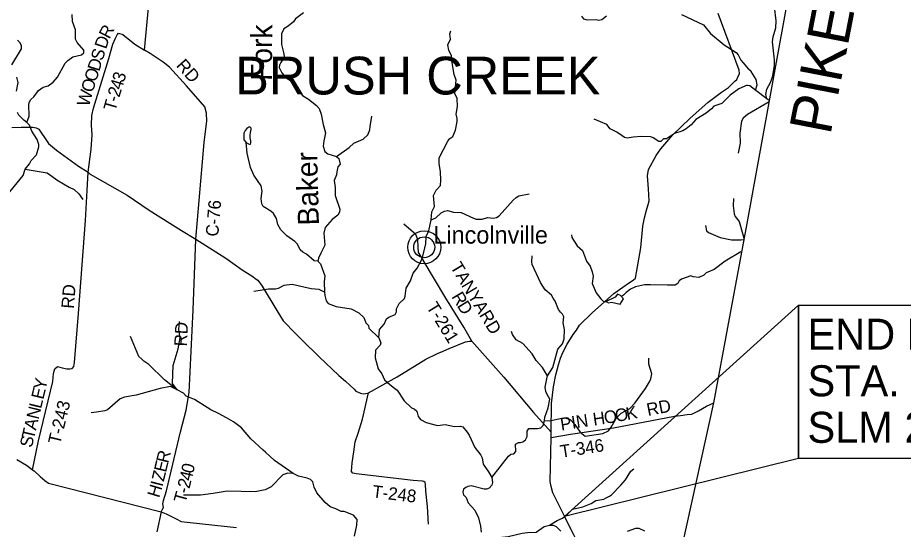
# Model space of a CAD drawing. Extents: x 0 to 34, y 0 to 22.
# Drawn here: x 3.854 to 7.846, y 16.923 to 19.231 of the extents above; entities that cross this region are included whole.
import ezdxf

# ---------------------------------------------------------------- set-up
doc = ezdxf.new("R2010")
doc.units = 0
for name, color, linetype in [('GM_X_Adjacent_County_Text', 7, 'Continuous'), ('GM_X_County', 7, 'Continuous'), ('GM_X_County_Road', 7, 'Continuous'), ('GM_X_County_Road_Text', 7, 'Continuous'), ('GM_X_Major_River', 7, 'Continuous'), ('GM_X_Major_River_Text', 7, 'Continuous'), ('GM_X_Minor_Lake', 7, 'Continuous'), ('GM_X_Minor_River', 7, 'Continuous'), ('GM_X_State_Route', 7, 'Continuous'), ('GM_X_Township_Road', 7, 'Continuous'), ('GM_X_Township_Road_Text', 7, 'Continuous'), ('GM_X_Township_ROW', 7, 'Continuous'), ('GM_X_Township_Text', 7, 'Continuous'), ('GM_X_Unincorporated', 7, 'Continuous'), ('GM_X_Unincorporated_Location', 7, 'Continuous'), ('GM_X_Unincorporated_Text', 7, 'Continuous'), ('SH_Data', 7, 'Continuous')]:
    doc.layers.add(name, color=color, linetype=linetype)

msp = doc.modelspace()

# ---------------------------------------------------------------- linework, layer by layer
at = {"layer": 'GM_X_County'}
msp.add_lwpolyline([(6.5214, 15.204), (6.5756, 15.5109), (6.5797, 15.5314), (6.7601, 16.3985), (6.794, 16.5922), (6.9912, 17.4939), (7.1423, 18.303), (7.4503, 19.9984), (7.5281, 20.392), (7.6111, 20.9006)], dxfattribs=at)
at = {"layer": 'GM_X_County_Road'}
for points in [[(4.6572, 18.2312), (4.6936, 18.6683), (4.7005, 18.7177), (4.7063, 18.7644), (4.7042, 18.8005), (4.6975, 18.8293), (4.6139, 18.9237), (4.5386, 19.0075), (4.5093, 19.0309), (4.4503, 19.0688), (4.4248, 19.0839), (4.4636, 19.5004)], [(3.8496, 17.2378), (3.8934, 17.2122), (3.9205, 17.1914), (3.9273, 17.1862), (3.9544, 17.161), (3.9761, 17.1429), (3.9918, 17.1304), (4.5003, 17.0015), (4.4801, 16.9118)]]:
    msp.add_lwpolyline(points, dxfattribs=at)
at = {"layer": 'GM_X_Major_River'}
for points in [[(5.1417, 19.2532), (5.1063, 19.2259), (5.0967, 19.2127), (5.073, 19.1928), (5.0532, 19.1805), (5.0432, 19.1579), (5.0427, 19.1098), (5.0536, 19.0672), (5.0542, 19.0547), (5.0396, 19.0287), (5.0342, 19.0162), (5.0326, 19.0064), (5.0444, 18.9824), (5.0631, 18.9594), (5.0879, 18.944), (5.1376, 18.8806), (5.1647, 18.864), (5.2004, 18.8345), (5.212, 18.8215), (5.2223, 18.796), (5.2305, 18.7493), (5.2419, 18.7109), (5.2367, 18.6882), (5.2344, 18.6757), (5.2307, 18.6515), (5.2388, 18.6268), (5.2519, 18.6164), (5.2915, 18.6043), (5.3017, 18.5954), (5.3071, 18.57), (5.2967, 18.558), (5.292, 18.5356), (5.2915, 18.5224), (5.2803, 18.4971), (5.2852, 18.4652), (5.2845, 18.4288), (5.3051, 18.3676), (5.3049, 18.3539), (5.2961, 18.34), (5.2713, 18.3205), (5.2399, 18.2841), (5.2336, 18.2587), (5.238, 18.2041), (5.2202, 18.1679), (5.209, 18.1453), (5.207, 18.1324), (5.2186, 18.1201), (5.2385, 18.0661), (5.2356, 18.0388), (5.2363, 17.993), (5.238, 17.9778), (5.2435, 17.9527), (5.2532, 17.9413), (5.2894, 17.9276), (5.3562, 17.9167), (5.3916, 17.8997), (5.4141, 17.8782), (5.4237, 17.8535), (5.4357, 17.8428), (5.4371, 17.8303), (5.4813, 17.7862)], [(5.4813, 17.7862), (5.4913, 17.7638), (5.4882, 17.7539), (5.466, 17.7314), (5.4649, 17.6958), (5.4788, 17.6471), (5.4948, 17.6246), (5.5074, 17.5976), (5.5307, 17.5754), (5.5524, 17.56), (5.5637, 17.5508), (5.5958, 17.5019), (5.6287, 17.4709), (5.6412, 17.4662), (5.6524, 17.4551), (5.6594, 17.4312), (5.6695, 17.4186), (5.6954, 17.405), (5.7456, 17.3905), (5.7801, 17.3951), (5.822, 17.386), (5.85, 17.3883), (5.8602, 17.3845), (5.88, 17.3608), (5.8893, 17.347), (5.9138, 17.2918), (5.941, 17.2567), (5.947, 17.2449), (5.9516, 17.2164), (5.9762, 17.1816), (5.9907, 17.1561), (5.9947, 17.1333), (5.9911, 17.1216), (5.9797, 17.1088), (5.9671, 17.1037), (5.9565, 17.103), (5.8984, 17.1187), (5.8833, 17.1159), (5.8738, 17.1106), (5.8638, 17.1032), (5.8596, 17.0903), (5.8636, 17.0785), (5.876, 17.0667), (5.8844, 17.0427), (5.9147, 17.0083), (5.931, 16.9736), (5.9401, 16.936), (5.9429, 16.9098)]]:
    msp.add_lwpolyline(points, dxfattribs=at)
at = {"layer": 'GM_X_Minor_Lake'}
for points in [[(4.8836, 18.6686), (4.8945, 18.6613), (4.8986, 18.6597), (4.9028, 18.6608), (4.9047, 18.6665), (4.9048, 18.6756), (4.9023, 18.6885), (4.902, 18.7006), (4.9029, 18.7123), (4.9061, 18.7263), (4.9054, 18.7332), (4.9005, 18.7381), (4.8952, 18.7371), (4.8865, 18.7315), (4.8792, 18.7221), (4.873, 18.71), (4.8725, 18.6971), (4.8735, 18.6888), (4.8723, 18.6797)], [(4.8723, 18.6797), (4.8836, 18.6686)], [(6.5706, 17.9775), (6.5581, 17.9833), (6.5463, 17.9705), (6.5071, 17.9497), (6.5173, 17.9439), (6.5305, 17.9468), (6.5694, 17.9388), (6.5844, 17.9629)], [(6.5844, 17.9629), (6.5706, 17.9775)]]:
    msp.add_lwpolyline(points, dxfattribs=at)
at = {"layer": 'GM_X_Minor_River'}
for points in [[(7.2301, 18.867), (7.2266, 18.8843), (7.2308, 18.9082), (7.248, 18.9409), (7.2583, 18.9689), (7.2651, 19.0158), (7.2647, 19.0409), (7.2561, 19.1226), (7.2591, 19.1446), (7.2707, 19.1846), (7.2731, 19.2172), (7.2654, 19.2807), (7.2735, 19.3656), (7.2935, 19.4041), (7.3308, 19.4654)], [(3.8944, 18.7587), (3.9056, 18.7874), (3.9038, 18.8371), (3.9055, 18.848), (3.9128, 18.8612), (3.9265, 18.874), (3.9476, 18.903), (3.9686, 18.9168), (3.9902, 18.9241), (4.0138, 18.9398), (4.0326, 18.962), (4.0673, 19.0257), (4.0791, 19.0381), (4.1024, 19.0546), (4.1418, 19.0629), (4.1513, 19.0731), (4.1514, 19.0841), (4.1223, 19.1196), (4.1145, 19.1341), (4.1149, 19.1765), (4.1005, 19.2142), (4.0997, 19.2449)], [(6.8465, 19.2454), (6.9451, 19.1985), (6.9765, 19.1603), (7.0388, 19.1078), (7.0918, 19.0743), (7.102, 19.0636), (7.1134, 19.0388), (7.1239, 19.0266), (7.1483, 18.9994)], [(6.3954, 19.2385), (6.4036, 19.2259), (6.4206, 19.2219), (6.4607, 19.2231), (6.4732, 19.2191), (6.4868, 19.2224), (6.5074, 19.2393)], [(5.4813, 17.7862), (5.4851, 17.8245), (5.5057, 17.8478), (5.5162, 17.8715), (5.5272, 17.8802), (5.5554, 17.8916), (5.5615, 17.9037), (5.5609, 17.917), (5.5729, 17.9419), (5.5966, 17.9644), (5.6008, 17.975), (5.6042, 18.0102), (5.6242, 18.0441), (5.637, 18.0788), (5.6543, 18.1014), (5.6739, 18.1365), (5.679, 18.1508), (5.694, 18.2098), (5.6947, 18.2435), (5.7063, 18.2696), (5.7181, 18.3191), (5.7204, 18.3547), (5.732, 18.3789), (5.7275, 18.4286), (5.7395, 18.4523), (5.7594, 18.4745), (5.7608, 18.4976), (5.7596, 18.5355), (5.7532, 18.5731), (5.7538, 18.5985), (5.7928, 18.6743), (5.802, 18.6852), (5.8146, 18.695), (5.8269, 18.7229), (5.8349, 18.7619), (5.835, 18.7759), (5.8295, 18.7957), (5.8363, 18.8297), (5.8352, 18.8665), (5.8237, 18.8897), (5.8307, 18.9492), (5.8207, 18.9743), (5.81, 19.0362), (5.8105, 19.0464), (5.8091, 19.0589), (5.7976, 19.0848), (5.7933, 19.1088), (5.8045, 19.1337), (5.8021, 19.1579), (5.8057, 19.1712)], [(3.827, 19.0179), (3.8712, 19.0906), (3.8706, 19.1054), (3.8631, 19.1187), (3.8534, 19.1302)], [(3.8485, 18.9001), (3.8553, 18.9391), (3.8495, 18.9634)], [(7.1814, 18.9038), (7.1836, 18.9187), (7.1874, 18.9274), (7.1832, 18.9521), (7.1599, 18.9882), (7.1483, 18.9994)], [(7.1424, 18.9265), (7.1046, 18.9096), (7.0657, 18.882), (7.0283, 18.8433), (6.9918, 18.8323), (6.9815, 18.8195), (6.9578, 18.8004), (6.9106, 18.7709), (6.8892, 18.7476), (6.8671, 18.7296), (6.8519, 18.7211), (6.8143, 18.7086), (6.7781, 18.685), (6.7649, 18.6837), (6.753, 18.6724), (6.7432, 18.6721), (6.7184, 18.689), (6.7074, 18.6929), (6.6655, 18.6953), (6.628, 18.6918), (6.6007, 18.6872), (6.589, 18.6911), (6.5788, 18.6972), (6.5548, 18.7142), (6.5243, 18.7296), (6.5097, 18.7487), (6.4528, 18.7728)], [(7.1415, 18.9266), (7.1536, 18.9249), (7.1814, 18.9038)], [(7.1814, 18.9038), (7.2301, 18.867)], [(7.2405, 18.8517), (7.1436, 18.7945)], [(7.2301, 18.867), (7.2418, 18.8585)], [(3.8186, 18.4448), (3.8788, 18.5196), (3.8873, 18.5468), (3.9065, 18.5709), (3.915, 18.586), (3.9387, 18.6119), (3.9493, 18.6482), (3.949, 18.6588), (3.9416, 18.6813), (3.9167, 18.719), (3.9075, 18.746), (3.8944, 18.7587), (3.8808, 18.7687), (3.8584, 18.7905), (3.8521, 18.8027)], [(5.2915, 18.6043), (5.3483, 18.6458), (5.3689, 18.6645), (5.4107, 18.6827), (5.4317, 18.7018), (5.441, 18.7245), (5.4431, 18.7396), (5.45, 18.7862)], [(7.1436, 18.7945), (7.1237, 18.7771), (7.1164, 18.7636), (7.1083, 18.7098), (7.1101, 18.6654), (7.1017, 18.62)], [(5.207, 18.1324), (5.1908, 18.1341), (5.1551, 18.1647), (5.1397, 18.1725), (5.1277, 18.1828), (5.1143, 18.2091), (5.1035, 18.221), (5.0667, 18.2471), (5.0404, 18.2735), (5.0267, 18.2983), (5.0209, 18.3245), (5.0064, 18.347), (4.9951, 18.3585), (4.9598, 18.379), (4.9535, 18.3915), (4.9514, 18.415), (4.9543, 18.4381), (4.9555, 18.4487), (4.9512, 18.4727), (4.918, 18.5204), (4.9025, 18.555), (4.8876, 18.6196), (4.8836, 18.6686)], [(3.8873, 18.5468), (3.9859, 18.5315), (4.034, 18.4965), (4.0852, 18.4664), (4.1089, 18.456), (4.1291, 18.4357), (4.1478, 18.4109)], [(5.7181, 18.3191), (5.7383, 18.328), (5.7631, 18.3505), (5.7772, 18.3583), (5.7912, 18.3609), (5.8184, 18.3541), (5.8535, 18.3523), (5.9085, 18.3267), (5.9206, 18.3217), (5.9471, 18.3218), (5.9713, 18.3295), (5.9985, 18.3258), (6.0114, 18.3287), (6.0248, 18.3369), (6.0879, 18.4083), (6.1001, 18.4196), (6.1134, 18.4267), (6.1593, 18.4364)], [(7.0811, 18.4148), (7.0789, 18.3818), (7.0827, 18.3465), (7.0883, 18.3332), (7.1058, 18.3107), (7.1219, 18.2521), (7.1268, 18.2367)], [(6.9543, 18.2928), (6.9586, 18.2689), (6.9684, 18.2612), (7.0207, 18.2387), (7.0721, 18.2288), (7.113, 18.2287), (7.1255, 18.2302)], [(6.3497, 18.2518), (6.3518, 18.2393), (6.3757, 18.2012), (6.3993, 18.1805), (6.4181, 18.1325), (6.4345, 18.1092), (6.4437, 18.0849), (6.4477, 18.0644), (6.4428, 18.0314), (6.4613, 17.9895), (6.4822, 17.9617), (6.4946, 17.9509), (6.5075, 17.9494)], [(7.1142, 18.1741), (7.0431, 18.1328), (6.9928, 18.0946), (6.9579, 18.0794), (6.946, 18.0697), (6.9247, 18.0589), (6.8987, 18.061), (6.8885, 18.0664), (6.846, 18.0517), (6.8361, 18.0442), (6.8299, 18.0318), (6.8177, 18.0235), (6.7833, 18.0239), (6.7069, 18.0258), (6.6789, 18.0253), (6.6383, 18.0166), (6.6159, 18.0054), (6.596, 17.9912), (6.5842, 17.9792), (6.5749, 17.9729)], [(5.9907, 17.1561), (6.0658, 17.2524), (6.0773, 17.261), (6.0905, 17.2628), (6.0993, 17.2733), (6.097, 17.3067), (6.1111, 17.3141), (6.1209, 17.3136), (6.1304, 17.317), (6.1422, 17.3267), (6.1503, 17.3418), (6.151, 17.3656), (6.1579, 17.3777), (6.1972, 17.3773), (6.2116, 17.3806), (6.2231, 17.3903), (6.2286, 17.4142), (6.2299, 17.4282), (6.2447, 17.4705), (6.2523, 17.5098), (6.24, 17.5308), (6.2341, 17.5437), (6.2312, 17.5639), (6.2388, 17.6021), (6.242, 17.6145), (6.2658, 17.653), (6.2878, 17.735), (6.3092, 17.7587), (6.3166, 17.7825), (6.3186, 17.8234), (6.3132, 17.8538), (6.3157, 17.8807), (6.3102, 17.8936), (6.3, 17.9017), (6.2918, 17.9143), (6.2763, 17.9516), (6.2681, 17.9661), (6.2603, 17.9794), (6.2318, 18.0036), (6.2109, 18.0356), (6.1724, 18.1171), (6.1706, 18.1293), (6.1728, 18.1562)], [(5.2363, 17.993), (5.2126, 18.0046), (5.1767, 18.008), (5.0902, 18.0266), (5.0538, 18.0232), (5.0284, 18.0094), (5.0151, 18.0058), (4.9848, 18.0065), (4.9174, 17.9954)], [(4.5725, 17.5511), (4.5512, 17.5805), (4.5546, 17.6612), (4.577, 17.7372), (4.5854, 17.7864), (4.5797, 17.8247), (4.5835, 17.8596)], [(6.242, 17.6145), (6.2192, 17.6519), (6.1908, 17.6848), (6.173, 17.7142), (6.1307, 17.7608), (6.1013, 17.777), (6.0838, 17.8015), (6.0794, 17.8152)], [(5.3714, 16.8912), (5.3829, 16.9415), (5.3839, 16.9662), (5.3667, 16.9868), (5.326, 17.0028), (5.312, 17.0033), (5.3003, 17.0095), (5.2875, 17.0153), (5.2623, 17.0246), (5.239, 17.0442), (5.202, 17.0878), (5.1901, 17.1129), (5.1835, 17.1364), (5.173, 17.1472), (5.1591, 17.1534), (5.1187, 17.1625), (5.095, 17.1737), (5.0108, 17.2329), (4.9711, 17.2705), (4.9598, 17.2797), (4.904, 17.3303), (4.8632, 17.3803), (4.8264, 17.4068), (4.7944, 17.4254), (4.7591, 17.4458), (4.724, 17.4613), (4.6511, 17.5083), (4.6138, 17.5234), (4.6007, 17.5361), (4.5725, 17.5511), (4.5154, 17.5968), (4.445, 17.6661), (4.4224, 17.6819), (4.4127, 17.6899), (4.4003, 17.7022), (4.3615, 17.7928)], [(6.2286, 17.4142), (6.2509, 17.4124), (6.3063, 17.424), (6.3199, 17.425), (6.3441, 17.4176), (6.3658, 17.3961), (6.3893, 17.3614), (6.411, 17.3434), (6.4917, 17.3547), (6.5165, 17.3673), (6.5295, 17.3831), (6.5534, 17.425), (6.574, 17.446), (6.6128, 17.468), (6.6354, 17.4912), (6.6841, 17.5575), (6.7021, 17.5872), (6.708, 17.6016), (6.7116, 17.6243), (6.6991, 17.6676), (6.6987, 17.6949)], [(4.5725, 17.5511), (4.5431, 17.5666), (4.4965, 17.5576), (4.3872, 17.5283), (4.3357, 17.5186), (4.3148, 17.5112), (4.2587, 17.461), (4.2465, 17.4565), (4.2083, 17.4512), (4.1852, 17.4484)], [(5.095, 17.1737), (5.0716, 17.1762), (5.0495, 17.1689), (4.9964, 17.1148), (4.969, 17.1007), (4.9235, 17.0913), (4.7976, 17.0944), (4.7351, 17.0837), (4.6775, 17.0763), (4.6007, 17.0767)], [(5.98, 16.8356), (5.9931, 16.8548), (6.0369, 16.8877), (6.0645, 16.8893), (6.1275, 16.905), (6.1513, 16.9074), (6.1915, 16.9089), (6.2269, 16.9347), (6.2508, 16.9409), (6.2858, 16.9629), (6.309, 16.9725), (6.3319, 16.9901), (6.3544, 17.0138), (6.4018, 17.0243), (6.4383, 17.0395), (6.46, 17.0529), (6.4964, 17.0578), (6.507, 17.0642), (6.5207, 17.0724), (6.5302, 17.078), (6.573, 17.1219), (6.593, 17.146), (6.6179, 17.1844), (6.6305, 17.196)], [(6.2508, 16.9409), (6.2678, 16.9407), (6.2806, 16.9349), (6.3016, 16.9138)], [(6.6031, 16.9135), (6.6404, 16.9279), (6.6544, 16.9282), (6.6792, 16.9162)]]:
    msp.add_lwpolyline(points, dxfattribs=at)
at = {"layer": 'GM_X_State_Route'}
for points in [[(6.2591, 17.3607), (6.2602, 17.4905), (6.2687, 17.5653), (6.2791, 17.6194), (6.291, 17.6641), (6.3005, 17.694), (6.3126, 17.7231), (6.33, 17.7578), (6.3582, 17.8011), (6.3732, 17.8211), (6.3868, 17.8441), (6.4435, 17.8992), (6.5412, 17.9869), (6.582, 18.0152), (6.6164, 18.0388), (6.6286, 18.047), (6.6386, 18.0556), (6.663, 18.1931), (6.6724, 18.2899), (6.6786, 18.3281), (6.6881, 18.3626), (6.6963, 18.3875), (6.7007, 18.4042), (6.6972, 18.4593), (6.6929, 18.5171), (6.6978, 18.5463), (6.7315, 18.6085), (6.7531, 18.6386), (6.8065, 18.7029), (6.8835, 18.7768), (6.9659, 18.8495), (7.027, 18.8943), (7.0572, 18.9156), (7.0871, 18.9448), (7.0959, 18.9527), (7.1006, 18.9633), (7.1072, 18.9795), (7.1063, 18.9936), (7.0115, 19.2499)], [(3.8268, 18.7356), (3.8692, 18.7363), (3.9223, 18.7364), (3.9374, 18.7339), (3.9495, 18.7281), (3.9864, 18.673)], [(3.9864, 18.673), (3.9865, 18.673), (3.9927, 18.6638), (4.0287, 18.6333), (4.1275, 18.5615), (4.1708, 18.5336), (4.1805, 18.5252), (4.3469, 18.4309), (4.4465, 18.3628), (4.5921, 18.2703), (4.6572, 18.2312), (4.7922, 18.1456), (4.8651, 18.0938), (4.9133, 18.0632), (4.9242, 18.0544), (4.9366, 18.047), (4.9556, 18.0194), (5.0225, 17.91), (5.0504, 17.863), (5.1062, 17.8061), (5.1376, 17.775), (5.1376, 17.775)], [(5.1376, 17.775), (5.2126, 17.7007), (5.301, 17.6169), (5.3314, 17.5903), (5.37, 17.5541), (5.3783, 17.5457), (5.399, 17.5371), (5.4107, 17.5339), (5.432, 17.5363), (5.4343, 17.5376), (5.5639, 17.6099), (5.6941, 17.6903), (5.7429, 17.7148), (5.7601, 17.722)], [(5.7601, 17.722), (5.7605, 17.7222), (5.7993, 17.7384), (5.8727, 17.7679), (5.891, 17.7719), (5.9005, 17.7718), (6.0452, 17.6086), (6.1786, 17.4498), (6.2591, 17.3607)], [(6.385, 16.8494), (6.2653, 17.0868), (6.2581, 17.1154), (6.2538, 17.1382), (6.2585, 17.3365), (6.2591, 17.3607)], [(6.3593, 16.9004), (6.319, 16.9802)]]:
    msp.add_lwpolyline(points, dxfattribs=at)
at = {"layer": 'GM_X_Township_Road'}
for points in [[(4.1959, 18.8225), (4.2007, 18.843), (4.2642, 19.0472), (4.2828, 19.1115), (4.2943, 19.1392), (4.3015, 19.1541), (4.3086, 19.1614), (4.3269, 19.155), (4.3817, 19.1109), (4.4248, 19.0839)], [(4.1271, 17.8964), (4.1271, 17.8965), (4.1597, 18.3162), (4.1672, 18.4517), (4.1708, 18.5336), (4.1849, 18.6375), (4.1887, 18.7024), (4.1861, 18.7461), (4.1881, 18.789), (4.1958, 18.8221), (4.1959, 18.8225)], [(5.6812, 18.1376), (5.6811, 18.1379), (5.6611, 18.1712), (5.6594, 18.1978), (5.6577, 18.2296), (5.6481, 18.252), (5.5941, 18.2995)], [(4.5003, 17.0015), (4.5048, 17.0098), (4.5105, 17.0209), (4.5084, 17.0376), (4.5102, 17.0528), (4.5251, 17.0965), (4.5879, 17.3626), (4.6127, 17.4595), (4.6269, 17.5397), (4.6446, 17.9122), (4.6572, 18.2312)], [(5.9005, 17.7718), (5.865, 17.8353), (5.7838, 17.9662), (5.6812, 18.1376)], [(3.9205, 17.1914), (3.9477, 17.3211), (4.0119, 17.5899), (4.0144, 17.6259), (4.021, 17.6472), (4.0324, 17.6564), (4.0536, 17.6505), (4.0757, 17.6464), (4.0882, 17.6461), (4.0992, 17.6477), (4.1071, 17.6565), (4.11, 17.6759), (4.1271, 17.8964)], [(5.3685, 17.2718), (5.3685, 17.2719), (5.3754, 17.3169), (5.3884, 17.3561), (5.4081, 17.42), (5.4343, 17.5376)], [(6.2585, 17.3365), (6.3463, 17.3524), (6.5388, 17.3809), (6.8141, 17.433), (6.841, 17.4366), (6.871, 17.4402), (6.8933, 17.4419), (6.9224, 17.4576), (6.9591, 17.4779), (6.9912, 17.4939)], [(5.6778, 17.139), (5.6775, 17.139), (5.637, 17.1427), (5.379, 17.173), (5.3646, 17.1752), (5.3577, 17.1828), (5.3608, 17.2223), (5.3685, 17.2718)], [(4.5003, 17.0015), (4.5224, 16.9929), (4.5471, 16.9801), (4.5677, 16.9692), (4.5912, 16.9584), (4.6307, 16.9529), (4.8402, 16.9314)]]:
    msp.add_lwpolyline(points, dxfattribs=at)
at = {"layer": 'GM_X_Township_ROW'}
msp.add_lwpolyline([(5.7049, 16.945), (5.7011, 17.0254), (5.6931, 17.0945), (5.6921, 17.1264), (5.6909, 17.1332), (5.6837, 17.1385), (5.6778, 17.139)], dxfattribs=at)
at = {"layer": 'GM_X_Unincorporated'}
for radius in [0.0744, 0.0472]:
    msp.add_circle((5.6862, 18.1951), radius, dxfattribs=at)
at = {"layer": 'GM_X_Unincorporated_Location'}
msp.add_line((5.6862, 18.1951), (5.6862, 18.1951), dxfattribs=at)
at = {"layer": 'SH_Data'}
for points in [[(6.319, 16.9802), (7.373, 17.9334), (7.373, 17.2427)], [(7.373, 17.9334), (9.0653, 17.9334), (9.0653, 17.2427), (7.373, 17.2427)]]:
    msp.add_lwpolyline(points, close=True, dxfattribs=at)

# ---------------------------------------------------------------- texts
at = {"layer": 'GM_X_Adjacent_County_Text'}
msp.add_text('PIKE COUNTY', height=0.189394, rotation=79.0186, dxfattribs=at).set_placement((7.5169, 18.6977))
at = {"layer": 'GM_X_County_Road_Text'}
for s, rotation, p in [('RD', 311.8782, (4.5648, 19.0132)), ('C-76', 85.208, (4.7574, 18.2417))]:
    msp.add_text(s, height=0.05682, rotation=rotation, dxfattribs=at).set_placement(p)
at = {"layer": 'GM_X_Major_River_Text'}
for s, rotation, p in [('Fork', 89.5778, (4.9993, 18.9461)), ('Baker', 91.4455, (5.2118, 18.2945))]:
    msp.add_text(s, height=0.09471, rotation=rotation, dxfattribs=at).set_placement(p)
at = {"layer": 'GM_X_Township_Road_Text'}
for s, height, rotation, p in [('R', 0.0568, 62.721, (4.267, 19.1316)), ('D', 0.0568, 71.5489, (4.252, 19.0864)), ('S', 0.0568, 72.9084, (4.2357, 19.0333)), ('D', 0.0568, 72.9122, (4.221, 18.9855)), ('O', 0.0568, 72.9072, (4.2063, 18.9377)), ('3', 0.0568, 72.9623, (4.3322, 18.9359)), ('O', 0.0568, 72.9257, (4.1916, 18.89)), ('4', 0.0568, 72.9788, (4.3219, 18.9024)), ('W', 0.0568, 74.6847, (4.1744, 18.8269)), ('2', 0.0568, 73.0166, (4.3117, 18.8689)), ('T', 0.0568, 74.0758, (4.2934, 18.806)), ('-', 0.0568, 73.1624, (4.305, 18.8466)), ('TANYARD', 0.05682, 300.963, (5.8019, 18.1071)), ('RD', 0.05682, 85.5641, (4.1067, 17.9166)), ('R', 0.0568, 300.7824, (5.8076, 17.9726)), ('T-261', 0.05682, 301.4812, (5.694, 17.9259)), ('D', 0.0568, 302.145, (5.8322, 17.9312)), ('RD', 0.05682, 87.0387, (4.6157, 17.7469)), ('Y', 0.0568, 77.8845, (3.9792, 17.5483)), ('E', 0.0568, 76.444, (3.9689, 17.5055)), ('L', 0.0568, 76.4247, (3.9589, 17.4641)), ('T-243', 0.05682, 76.373, (4.0448, 17.3025)), ('RD', 0.05682, 10.9226, (6.6947, 17.4335)), ('N', 0.0568, 76.4205, (3.9472, 17.4155)), ('H', 0.0568, 8.4232, (6.4507, 17.3904)), ('O', 0.0568, 9.3261, (6.5012, 17.3978)), ('O', 0.0568, 10.5559, (6.5518, 17.4062)), ('K', 0.0568, 10.8076, (6.6012, 17.4154)), ('A', 0.0568, 76.4355, (3.9355, 17.3669)), ('PIN', 0.05682, 8.9744, (6.3041, 17.3677)), ('T', 0.0568, 76.8088, (3.9258, 17.3256)), ('S', 0.0568, 77.9865, (3.9179, 17.2884)), ('T-346', 0.05682, 8.8284, (6.3036, 17.2451)), ('R', 0.0568, 76.307, (4.5321, 17.2179)), ('E', 0.0568, 76.3053, (4.522, 17.1766)), ('0', 0.0568, 76.3757, (4.6444, 17.1714)), ('Z', 0.0568, 76.2259, (4.5119, 17.1352)), ('4', 0.0568, 76.3422, (4.6361, 17.1374)), ('I', 0.0568, 75.5223, (4.5059, 17.1119)), ('2', 0.0568, 76.1735, (4.6277, 17.1032)), ('H', 0.0568, 73.3681, (4.491, 17.0618)), ('T', 0.0568, 74.5396, (4.6103, 17.0379)), ('-', 0.0568, 75.8628, (4.622, 17.0803)), ('T-248', 0.05682, 353.2248, (5.4498, 17.0661))]:
    msp.add_text(s, height=height, rotation=rotation, dxfattribs=at).set_placement(p)
at = {"layer": 'GM_X_Township_Text'}
msp.add_text('BRUSH CREEK', height=0.170455, rotation=0, dxfattribs=at).set_placement((4.834, 18.8845))
at = {"layer": 'GM_X_Unincorporated_Text'}
msp.add_text('Lincolnville', height=0.078977, rotation=0, dxfattribs=at).set_placement((5.7273, 18.2115))
at = {"layer": 'SH_Data'}
for s, p in [('END PROJECT', (7.414, 17.7327)), ('STA. 107+00', (7.414, 17.5227)), ('SLM 2.03', (7.414, 17.3127))]:
    msp.add_text(s, height=0.14, dxfattribs=at).set_placement(p)

doc.saveas('drawing.dxf')
